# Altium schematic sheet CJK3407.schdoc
size 127 x 101 mm
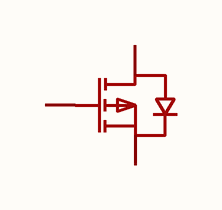
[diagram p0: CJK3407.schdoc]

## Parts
Q?  cjk3407  [SOT-23-3_L2.9-W1.6-P1.90-LS2.8-BR]  (value not drawn)

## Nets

Not connected (* = marked no-connect by the designer): Q? 1(G) 2(S) 3(D)

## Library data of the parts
Q? = cjk3407: 数量:1个P沟道;漏源电压(Vdss):30V;连续漏极电流(Id):4.1A;导通电阻(RDS(on)):60mΩ@10V;耗散功率(Pd):300mW;阈值电压(Vgs(th)):1.4V;; Manufacturer: CJ(江苏长电/长晶); AddInBom: yes; ModelId: 89cb27a44ab2466697082bb9fd73a7d0; ModelName: SOT-23-3L_L2.9-W1.6-H1.1-LS2.8-P0.95; ModelTransform: 114.173,110.236,0,90,0,0,0,0,0; Number: 1个P沟道; Drain to Source Voltage: 30V; Current - Continuous Drain(Id): 4.1A; Pd - Power Dissipation: 300mW; Gate Threshold Voltage (Vgs(th)): 1.4V; Input Capacitance(Ciss): 700pF; Reverse Transfer Capacitance (Crss@Vds): 75pF; Type: P沟道; Output Capacitance(Coss): 120pF; Vgs: ±20V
